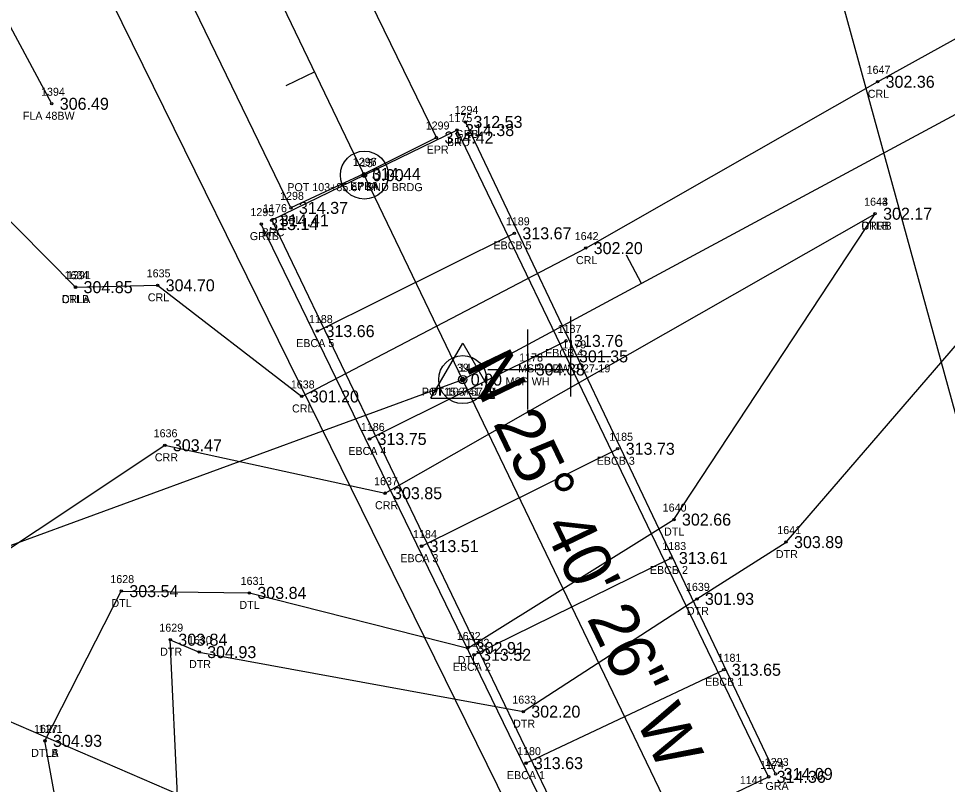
# Model space of a CAD drawing. Extents: x 1865045 to 1867370, y 910391 to 914218.
# Drawn here: x 1866324 to 1866440, y 911038.9 to 911134.6 of the extents above; entities that cross this region are included whole.
import ezdxf

# ---------------------------------------------------------------- set-up
doc = ezdxf.new("R2010")
doc.units = 0
for name, color, linetype in [('RD_EX_Bridge', 7, 'Continuous'), ('RD_EX_Bridge_txCode', 7, 'Continuous'), ('RD_EX_Fence_Other', 7, 'Continuous'), ('RD_EX_Fence_Other_txCode', 7, 'Continuous'), ('RD_EX_GuardRail', 7, 'Continuous'), ('RD_EX_GuardRail_txCode', 7, 'Continuous'), ('RD_EX_H2O', 7, 'Continuous'), ('RD_EX_H2O_txCode', 7, 'Continuous'), ('RD_EX_Road', 7, 'Continuous'), ('RD_EX_Road_txCode', 7, 'Continuous'), ('RD_EX_TX_Bridge_ELEV', 7, 'Continuous'), ('RD_EX_TX_Fence_Other_ELEV', 7, 'Continuous'), ('RD_EX_TX_GuardRail_ELEV', 7, 'Continuous'), ('RD_EX_TX_H2O_ELEV', 7, 'Continuous'), ('RD_EX_TX_Misc_ELEV', 7, 'Continuous'), ('RD_EX_TX_Road_ELEV', 7, 'Continuous'), ('RD_EX_VEG', 7, 'Continuous'), ('RD_HC_Cl', 7, 'Continuous'), ('RD_HC_Data', 7, 'Continuous'), ('RD_HC_Data_Tic', 7, 'Continuous'), ('RD_HC_Survey_ELEV', 7, 'Continuous'), ('RD_HC_txCode', 7, 'Continuous'), ('RD_SMD_Locator', 7, 'Continuous')]:
    doc.layers.add(name, color=color, linetype=linetype)

msp = doc.modelspace()

# ---------------------------------------------------------------- linework, layer by layer
at = {"layer": 'RD_EX_Bridge'}
for p, q in [((1866361.31, 911095.57), (1866385.91, 911107.79)), ((1866367.81, 911082.09), (1866392.37, 911094.35)), ((1866374.31, 911068.69), (1866398.82, 911080.86)), ((1866380.87, 911055.11), (1866405.46, 911067.21)), ((1866387.35, 911041.57), (1866412.08, 911053.24))]:
    msp.add_line(p, q, dxfattribs=at)
msp.add_lwpolyline([(1866394.37, 911028.71), (1866417.68, 911039.86), (1866378.75, 911120.69), (1866355.6, 911109.43), (1866394.37, 911028.71)], dxfattribs=at)
at = {"layer": 'RD_EX_Fence_Other'}
for points in [[(1866328.11, 911123.98), (1866317.73, 911143.27), (1866292.21, 911196.64), (1866254.72, 911273.66), (1866198.8, 911388.88), (1866160.41, 911467.37), (1866132.32, 911522.75), (1866123.76, 911516.89), (1866120.96, 911520.71)], [(1866495.48, 910749.21), (1866508.82, 910756.58), (1866493.03, 910785.29), (1866469.81, 910829.93), (1866443.69, 910882.22), (1866422.34, 910922.89), (1866379.46, 911022.29), (1866316.24, 911049.61), (1866298.72, 911056.62), (1866262.33, 911070.09)]]:
    msp.add_lwpolyline(points, dxfattribs=at)
at = {"layer": 'RD_EX_GuardRail'}
for p, q in [((1866418.55, 911040.22), (1866379.79, 911121.71)), ((1866393.65, 911027.94), (1866354.28, 911108.94))]:
    msp.add_line(p, q, dxfattribs=at)
at = {"layer": 'RD_EX_H2O'}
for p, q in [((1866392.98, 911087.41), (1866392.98, 911097.41)), ((1866387.58, 911085.77), (1866387.58, 911095.77)), ((1866387.98, 911092.41), (1866397.98, 911092.41)), ((1866382.58, 911090.77), (1866392.58, 911090.77))]:
    msp.add_line(p, q, dxfattribs=at)
for points in [[(1866331.08, 911101.06), (1866341.34, 911101.29), (1866359.35, 911087.4), (1866394.82, 911105.94), (1866431.29, 911126.73), (1866483.98, 911155.87), (1866535.56, 911200.19), (1866648.32, 911256.97), (1866711.23, 911325.93), (1866820.03, 911411.25)], [(1866289.66, 911132.29), (1866295.42, 911133.75), (1866306.06, 911126.35), (1866331.08, 911101.06)], [(1865881.51, 910820.06), (1865958.27, 910871.4), (1866021.41, 910928.56), (1866077.02, 910947.47), (1866128.62, 910963.47), (1866198.85, 910988.48), (1866262.44, 911028.2), (1866342.24, 911081.3), (1866369.75, 911075.31), (1866430.98, 911110.24)], [(1866327.26, 911044.36), (1866336.8, 911063.07), (1866352.8, 911062.85), (1866380.08, 911055.96), (1866405.85, 911072.01), (1866430.98, 911110.24)], [(1866343.87, 911036.65), (1866342.92, 911057), (1866346.53, 911055.45), (1866387.02, 911048.01), (1866408.72, 911062.1), (1866419.85, 911069.2), (1866443.37, 911096.45)], [(1866349.43, 910920.4), (1866342.95, 910957.57), (1866327.26, 911044.36)]]:
    msp.add_lwpolyline(points, dxfattribs=at)
for centre in [(1866392.98, 911092.41), (1866387.58, 911090.77)]:
    msp.add_circle(centre, 0.15, dxfattribs=at)
at = {"layer": 'RD_EX_Road'}
for points in [[(1866367.09, 911115.22), (1866376.17, 911119.76), (1866330.4, 911213.7), (1866286.92, 911304.16), (1866242.4, 911396.3), (1866197.74, 911488.67), (1866154.31, 911579.91), (1866143.08, 911603.17), (1866108.16, 911674.25), (1866059.64, 911774.84), (1866048.38, 911798.67), (1866045.99, 911803.62)], [(1866367.09, 911115.22), (1866357.99, 911110.97), (1866313.12, 911203.44), (1866268.86, 911295.9), (1866224.24, 911388.66), (1866179.87, 911480.6), (1866149.84, 911543.41), (1866142.18, 911559.37), (1866135.93, 911572.05), (1866096.83, 911651.51), (1866089.65, 911665.46), (1866062.87, 911720.39), (1866042.14, 911765.69), (1866027.93, 911795.04)]]:
    msp.add_lwpolyline(points, dxfattribs=at)
at = {"layer": 'RD_EX_VEG'}
for points in [[(1866452.86, 910898.44), (1866327.79, 911152.66), (1866304.37, 911199.34), (1866261.27, 911293.31), (1866216.38, 911387.21), (1866171.77, 911477.63), (1866125.33, 911567.24), (1866081.32, 911550.6)], [(1866477.92, 910951.04), (1866423.33, 911149.72), (1866377.08, 911237.62), (1866329.48, 911327.65), (1866279.59, 911419.45), (1866252.34, 911486.96)]]:
    msp.add_lwpolyline(points, dxfattribs=at)
at = {"layer": 'RD_HC_Cl'}
for p, q in [((1866502.49, 910833.56), (1866280.52, 911295.32)), ((1866379.46, 911089.5), (1866659.15, 911240.15)), ((1866069.86, 910975.96), (1866379.46, 911089.5))]:
    msp.add_line(p, q, dxfattribs=at)
at = {"layer": 'RD_HC_Data'}
for p, q in [((1866375.49, 911087.2), (1866379.46, 911094.08)), ((1866379.46, 911094.08), (1866383.43, 911087.2)), ((1866375.49, 911087.2), (1866383.43, 911087.2))]:
    msp.add_line(p, q, dxfattribs=at)
for centre, radius in [((1866367.17, 911115.06), 3), ((1866367.17, 911115.06), 0.282), ((1866379.46, 911089.5), 3), ((1866379.46, 911089.5), 0.529), ((1866379.46, 911089.5), 0.282)]:
    msp.add_circle(centre, radius, dxfattribs=at)
at = {"layer": 'RD_HC_Data_Tic'}
for p, q in [((1866360.97, 911127.97), (1866357.36, 911126.24)), ((1866401.8, 911101.53), (1866399.91, 911105.05))]:
    msp.add_line(p, q, dxfattribs=at)
at = {"layer": 'RD_SMD_Locator'}
for centre in [(1866431.29, 911126.73), (1866328.11, 911123.98), (1866379.79, 911121.71), (1866378.75, 911120.69), (1866376.17, 911119.76), (1866367.09, 911115.22), (1866367.09, 911115.22), (1866367.17, 911115.06), (1866357.99, 911110.97), (1866430.98, 911110.24), (1866430.98, 911110.24), (1866354.28, 911108.94), (1866355.6, 911109.43), (1866385.91, 911107.79), (1866394.82, 911105.94), (1866331.08, 911101.06), (1866331.08, 911101.06), (1866341.34, 911101.29), (1866361.31, 911095.57), (1866392.37, 911094.35), (1866379.46, 911089.5), (1866379.46, 911089.5), (1866359.35, 911087.4), (1866342.24, 911081.3), (1866367.81, 911082.09), (1866398.82, 911080.86), (1866369.75, 911075.31), (1866405.85, 911072.01), (1866374.31, 911068.69), (1866419.85, 911069.2), (1866405.46, 911067.21), (1866336.8, 911063.07), (1866352.8, 911062.85), (1866408.72, 911062.1), (1866342.92, 911057), (1866346.53, 911055.45), (1866380.08, 911055.96), (1866380.87, 911055.11), (1866412.08, 911053.24), (1866387.02, 911048.01), (1866327.26, 911044.36), (1866327.26, 911044.36), (1866387.35, 911041.57), (1866417.68, 911039.86), (1866418.55, 911040.22)]:
    msp.add_circle(centre, 0.15, dxfattribs=at)

# ---------------------------------------------------------------- texts
at = {"layer": 'RD_EX_Bridge_txCode'}
for s, p in [('1175', (1866377.68, 911121.69)), ('BRC', (1866377.49, 911118.69)), ('1176', (1866354.52, 911110.43)), ('1189', (1866384.85, 911108.79)), ('BRC', (1866354.35, 911107.43)), ('EBCB 5', (1866383.29, 911105.79)), ('1188', (1866360.24, 911096.57)), ('1187', (1866391.31, 911095.35)), ('EBCA 5', (1866358.65, 911093.57)), ('EBCB 4', (1866389.75, 911092.35)), ('1186', (1866366.73, 911083.09)), ('1185', (1866397.76, 911081.86)), ('EBCA 4', (1866365.16, 911080.09)), ('EBCB 3', (1866396.2, 911078.86)), ('1184', (1866373.25, 911069.69)), ('1183', (1866404.4, 911068.21)), ('EBCA 3', (1866371.66, 911066.69)), ('EBCB 2', (1866402.84, 911065.21)), ('1182', (1866379.81, 911056.11)), ('1181', (1866411.3, 911054.24)), ('EBCA 2', (1866378.22, 911053.11)), ('EBCB 1', (1866409.74, 911051.24)), ('1180', (1866386.25, 911042.57)), ('1174', (1866416.62, 911040.86)), ('EBCA 1', (1866384.98, 911039.57))]:
    msp.add_text(s, height=1, dxfattribs=at).set_placement(p)
at = {"layer": 'RD_EX_Fence_Other_txCode'}
for s, p in [('1394', (1866326.77, 911124.98)), ('FLA 48BW', (1866324.5, 911121.98))]:
    msp.add_text(s, height=1, dxfattribs=at).set_placement(p)
at = {"layer": 'RD_EX_GuardRail_txCode'}
for s, p in [('1294', (1866378.44, 911122.71)), ('GRB', (1866378.53, 911119.71)), ('1295', (1866352.93, 911109.94)), ('GR1B', (1866352.86, 911106.94)), ('1293', (1866417.2, 911041.22)), ('GRA', (1866417.28, 911038.22))]:
    msp.add_text(s, height=1, dxfattribs=at).set_placement(p)
at = {"layer": 'RD_EX_H2O_txCode'}
for s, p in [('1647', (1866429.92, 911127.73)), ('CRL', (1866430.06, 911124.73)), ('1643', (1866429.61, 911111.24)), ('1644', (1866429.61, 911111.24)), ('CRRB', (1866429.26, 911108.24)), ('DTLB', (1866429.27, 911108.24)), ('1642', (1866393.45, 911106.94)), ('CRL', (1866393.6, 911103.94)), ('1635', (1866339.97, 911102.29)), ('1634', (1866329.71, 911102.06)), ('1391', (1866330.02, 911102.06)), ('CRLA', (1866329.36, 911099.06)), ('DTLB', (1866329.36, 911099.06)), ('CRL', (1866340.11, 911099.29)), ('1179', (1866391.91, 911093.41)), ('1178', (1866386.51, 911091.77)), ('MSP ODW 3-27-19', (1866386.38, 911090.41)), ('1638', (1866357.98, 911088.4)), ('MSP WH', (1866384.81, 911088.77)), ('CRL', (1866358.13, 911085.4)), ('1636', (1866340.84, 911082.3)), ('CRR', (1866340.99, 911079.3)), ('1637', (1866368.38, 911076.31)), ('CRR', (1866368.5, 911073.31)), ('1640', (1866404.44, 911073.01)), ('DTL', (1866404.61, 911070.01)), ('1641', (1866418.76, 911070.2)), ('DTR', (1866418.58, 911067.2)), ('1628', (1866335.43, 911064.07)), ('1631', (1866351.71, 911063.85)), ('1639', (1866407.35, 911063.1)), ('DTL', (1866335.56, 911061.07)), ('DTL', (1866351.55, 911060.85)), ('DTR', (1866407.46, 911060.1)), ('1629', (1866341.55, 911058)), ('1632', (1866378.71, 911056.96)), ('1630', (1866345.12, 911056.45)), ('DTR', (1866341.65, 911055)), ('DTR', (1866345.26, 911053.45)), ('DTL', (1866378.83, 911053.96)), ('1633', (1866385.65, 911049.01)), ('1627', (1866325.89, 911045.36)), ('1171', (1866326.48, 911045.36)), ('DTR', (1866385.75, 911046.01)), ('DTLA', (1866325.53, 911042.36)), ('DTLB', (1866325.54, 911042.36))]:
    msp.add_text(s, height=1, dxfattribs=at).set_placement(p)
at = {"layer": 'RD_EX_Road_txCode'}
for s, p in [('1299', (1866374.83, 911120.76)), ('EPR', (1866374.95, 911117.76)), ('1296', (1866365.72, 911116.22)), ('1297', (1866365.74, 911116.22)), ('EPRA', (1866365.37, 911113.22)), ('EPLA', (1866365.4, 911113.22)), ('1298', (1866356.64, 911111.97)), ('EPL', (1866356.78, 911108.97)), ('1141', (1866414.08, 911038.95))]:
    msp.add_text(s, height=1, dxfattribs=at).set_placement(p)
at = {"layer": 'RD_EX_TX_Bridge_ELEV'}
for s, p in [('314.38', (1866379.75, 911119.94)), ('314.41', (1866356.6, 911108.68)), ('313.67', (1866386.91, 911107.04)), ('313.66', (1866362.31, 911094.82)), ('313.76', (1866393.37, 911093.6)), ('313.75', (1866368.81, 911081.34)), ('313.73', (1866399.82, 911080.11)), ('313.51', (1866375.31, 911067.94)), ('313.61', (1866406.46, 911066.46)), ('313.52', (1866381.87, 911054.36)), ('313.65', (1866413.08, 911052.49)), ('313.63', (1866388.35, 911040.82)), ('314.36', (1866418.68, 911039.11))]:
    msp.add_text(s, height=1.5, dxfattribs=at).set_placement(p)
at = {"layer": 'RD_EX_TX_Fence_Other_ELEV'}
msp.add_text('306.49', height=1.5, dxfattribs=at).set_placement((1866329.11, 911123.23))
at = {"layer": 'RD_EX_TX_GuardRail_ELEV'}
for s, p in [('312.53', (1866380.79, 911120.96)), ('313.14', (1866355.28, 911108.19)), ('314.09', (1866419.55, 911039.47))]:
    msp.add_text(s, height=1.5, dxfattribs=at).set_placement(p)
at = {"layer": 'RD_EX_TX_H2O_ELEV'}
for s, p in [('302.36', (1866432.29, 911125.98)), ('302.17', (1866431.98, 911109.49)), ('302.17', (1866431.98, 911109.49)), ('302.20', (1866395.82, 911105.19)), ('304.70', (1866342.34, 911100.54)), ('304.85', (1866332.08, 911100.31)), ('304.85', (1866332.08, 911100.31)), ('301.20', (1866360.35, 911086.65)), ('303.47', (1866343.24, 911080.55)), ('303.85', (1866370.75, 911074.56)), ('302.66', (1866406.85, 911071.26)), ('303.89', (1866420.85, 911068.45)), ('303.54', (1866337.8, 911062.32)), ('303.84', (1866353.8, 911062.1)), ('301.93', (1866409.72, 911061.35)), ('303.84', (1866343.92, 911056.25)), ('304.93', (1866347.53, 911054.7)), ('302.91', (1866381.08, 911055.21)), ('302.20', (1866388.02, 911047.26)), ('304.93', (1866328.26, 911043.61)), ('304.93', (1866328.26, 911043.61))]:
    msp.add_text(s, height=1.5, dxfattribs=at).set_placement(p)
at = {"layer": 'RD_EX_TX_Misc_ELEV'}
for s, p in [('301.35', (1866393.98, 911091.66)), ('304.38', (1866388.58, 911090.02))]:
    msp.add_text(s, height=1.5, dxfattribs=at).set_placement(p)
at = {"layer": 'RD_EX_TX_Road_ELEV'}
for s, p in [('314.42', (1866377.17, 911119.01)), ('314.44', (1866368.09, 911114.47)), ('314.44', (1866368.09, 911114.47)), ('314.37', (1866358.99, 911110.22))]:
    msp.add_text(s, height=1.5, dxfattribs=at).set_placement(p)
at = {"layer": 'RD_HC_Data'}
msp.add_text('N 25%%d 40\' 26" W', height=6, rotation=295.674, dxfattribs=at).set_placement((1866379.71, 911091.3))
at = {"layer": 'RD_HC_Survey_ELEV'}
for p in [(1866368.17, 911114.31), (1866380.46, 911088.75), (1866380.46, 911088.75)]:
    msp.add_text('0.00', height=1.5, dxfattribs=at).set_placement(p)
at = {"layer": 'RD_HC_txCode'}
for s, p in [('15', (1866366.73, 911116.06)), ('POT 103+85.67 END BRDG', (1866357.54, 911113.06)), ('39', (1866378.73, 911090.5)), ('14', (1866379.01, 911090.5)), ('POT 103+57.31', (1866374.34, 911087.5)), ('PI 15+741.63', (1866375.49, 911087.5))]:
    msp.add_text(s, height=1, dxfattribs=at).set_placement(p)

doc.saveas('drawing.dxf')
